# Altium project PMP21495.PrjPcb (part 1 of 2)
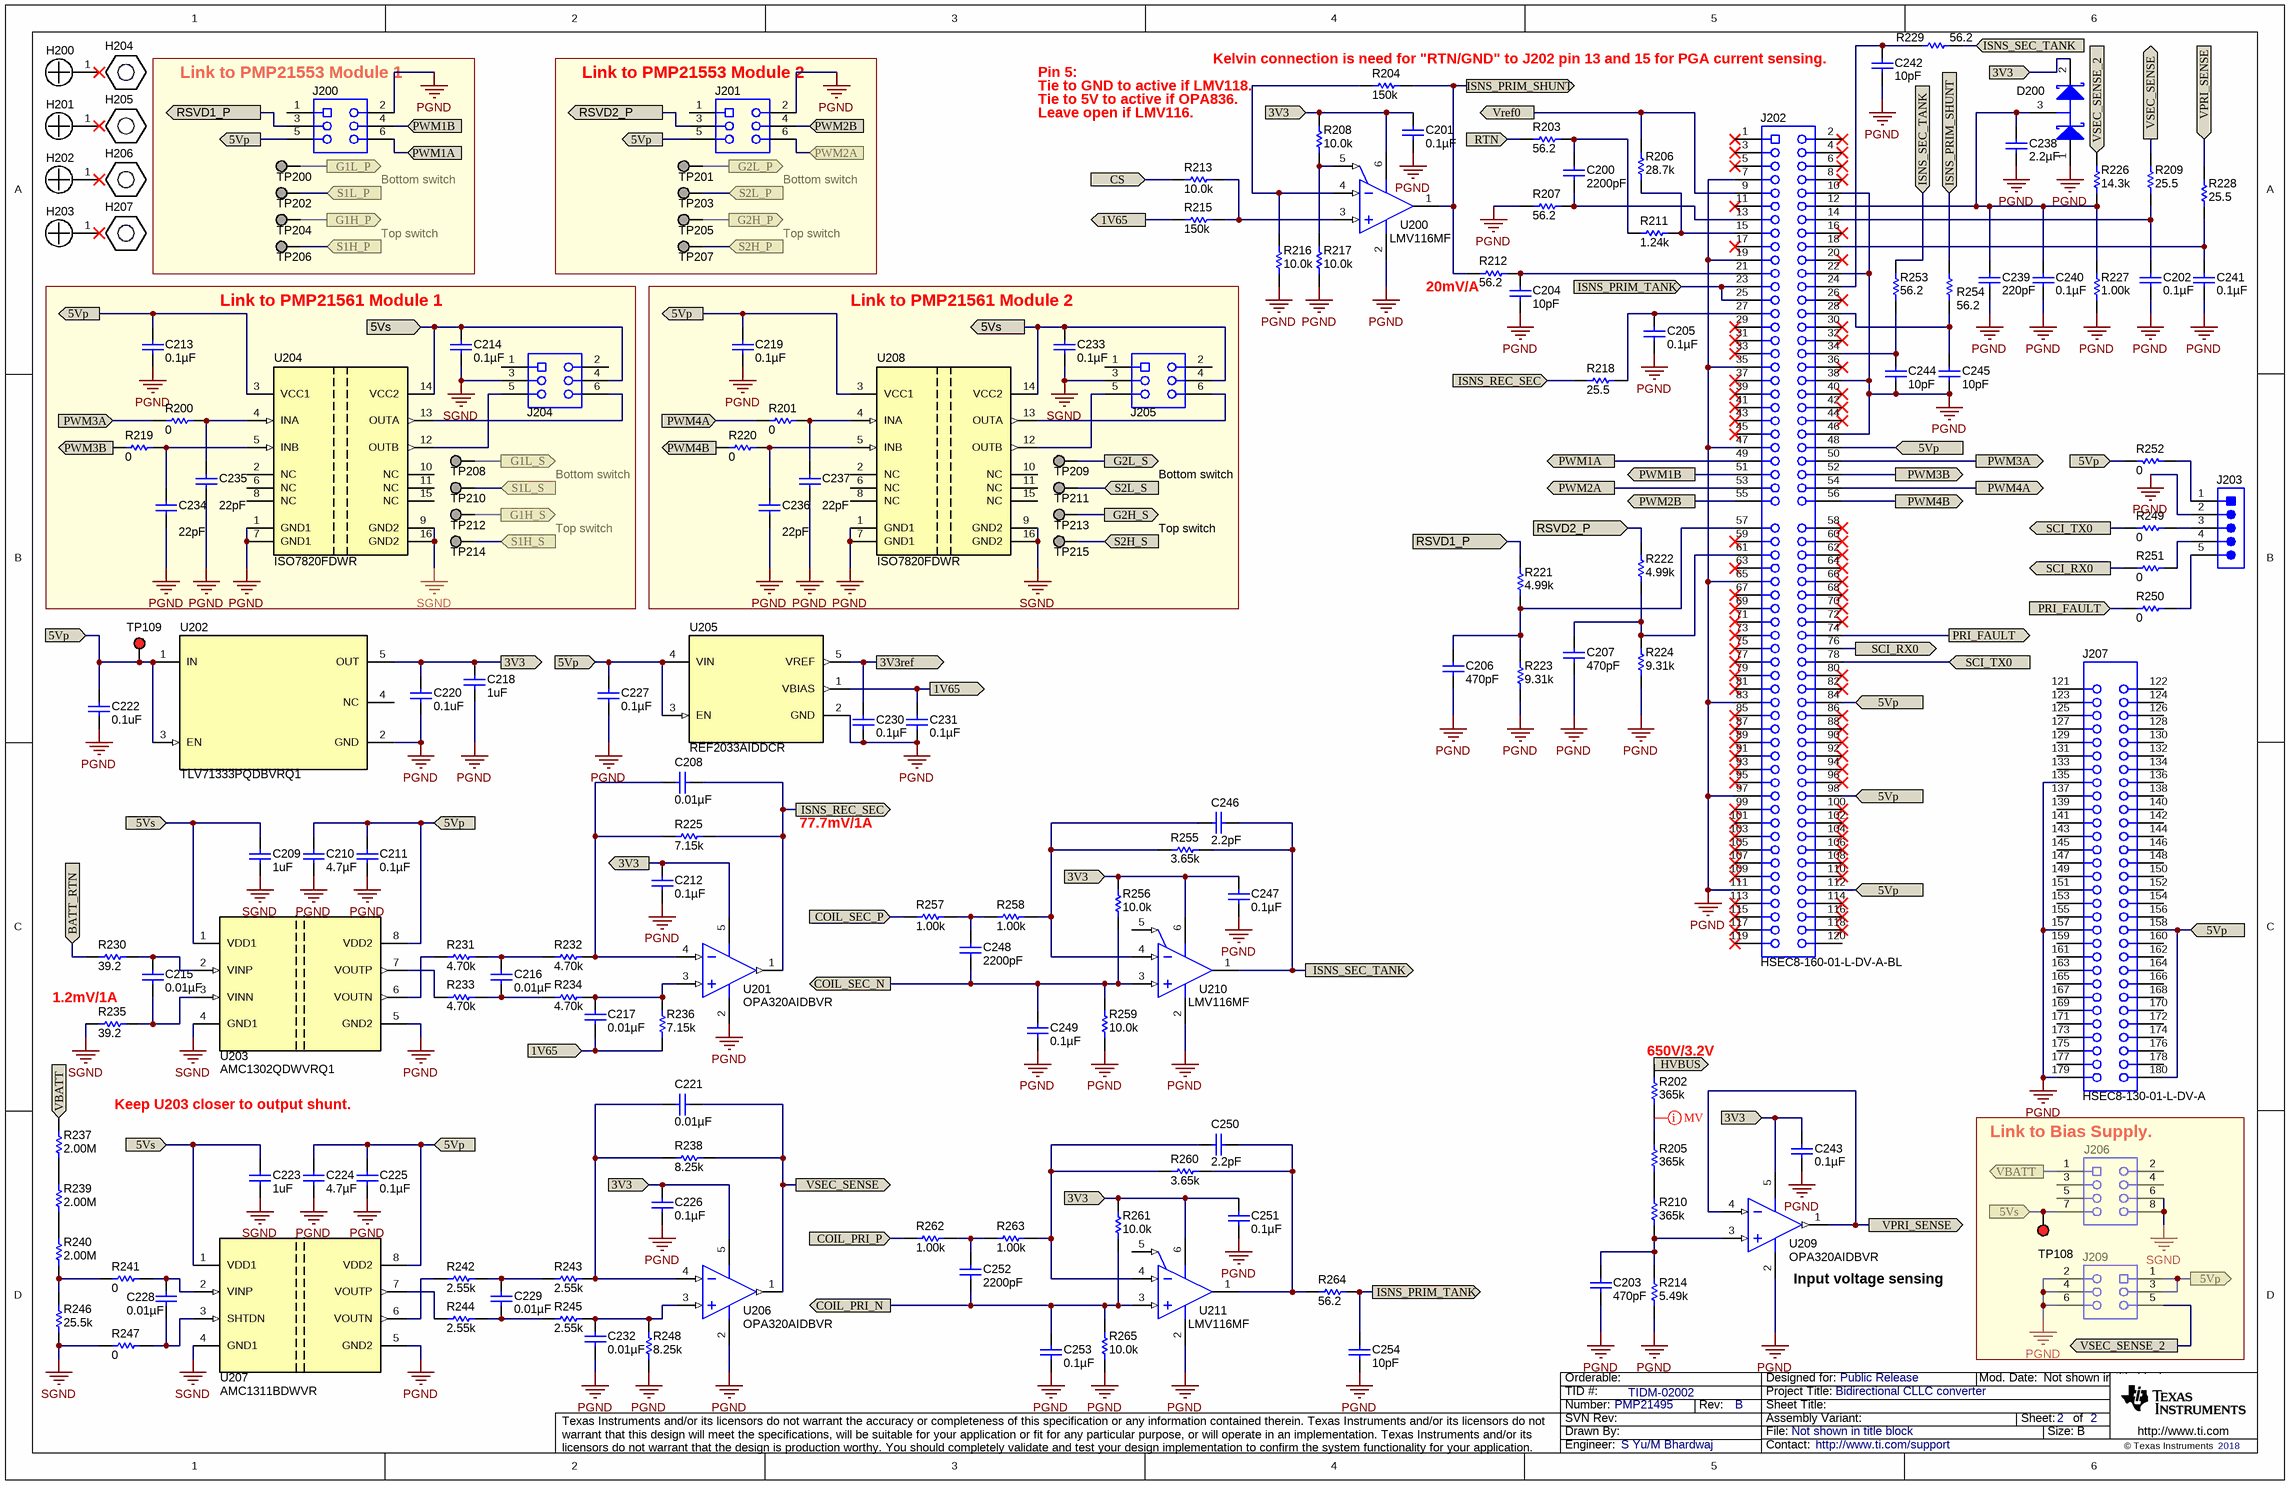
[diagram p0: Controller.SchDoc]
TID: TIDM-02002; TechSupport: http://www.ti.com/support; SCH_Rev: B; PRJ_Title: Bidirectional CLLC converter; PRJ_Number: PMP21495; PRJ_Engineer: S Yu/M Bhardwaj; PRJ_Customer: Public Release; PCB_Rev: B; PCB_Layout: Sheng-Yang Yu; CopyrightYear: 2018
2 sheets, 318 parts. Net scope: flat (ports and power ports of the same name join across sheets).
Board file: PMP21495.PcbDoc
Sheets:
  Controller.SchDoc
  PowerStage.SchDoc

## Sheet Controller.SchDoc
size 431 x 279 mm; Date: Not shown in title block; ApprovedBy: Not shown in title block; CheckedBy: Not shown in title block; Author: Not shown in title block; CompanyName: Not shown in title block; Engineer: Not shown in title block; Organization: Not shown in title block; Address1: Not shown in title block; Address2: Not shown in title block; Address3: Not shown in title block; Address4: Not shown in title block; DocumentNumber: 2; Revision: Use project parameter SCH_Rev; SheetNumber: 2; SheetTotal: 2; PageSetup: Record=PageOptions¦CenterHorizontal=True¦CenterVertical=True¦PrintScale=1.00¦XCorrection=1.00¦YCorrection=1.00¦PrintKind=0¦BorderSize=5000000¦LeftOffset=0¦BottomOffset=0¦Orientation=2¦PaperLength=1000¦PaperWidth=1000¦Scale=100¦PaperSource=15¦PrintQuality=600¦MediaType=1¦DitherType=10¦PaperKind=Letter¦PrintScaleMode=1

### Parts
C200  ValueDisplayed: 2200pF  [0402]  (hidden comment: C0402C222K9RAC7867)
C201  ValueDisplayed: 0.1µF  [0603]  (hidden comment: 06033C104JAT2A)
C202  ValueDisplayed: 0.1µF  [0603]  (hidden comment: 06033C104JAT2A)
C203  ValueDisplayed: 470pF  [0402]  (hidden comment: CGA2B2X7R1H471K050BA)
C204  ValueDisplayed: 10pF  [0603]  (hidden comment: C0603C100J5GACTU)
C205  ValueDisplayed: 0.1µF  [0603]  (hidden comment: 06033C104JAT2A)
C206  ValueDisplayed: 470pF  [0402]  (hidden comment: CGA2B2X7R1H471K050BA)
C207  ValueDisplayed: 470pF  [0402]  (hidden comment: CGA2B2X7R1H471K050BA)
C208  ValueDisplayed: 0.01µF  [0402]  (hidden comment: GRM155R61A103KA01D)
C209  ValueDisplayed: 1uF  [0603]  (hidden comment: C1608X7R1E105K080AB)
C210  ValueDisplayed: 4.7µF  [0603]  (hidden comment: CGB3B1X5R1A475K055AC)
C211  ValueDisplayed: 0.1µF  [0603]  (hidden comment: 06033C104JAT2A)
C212  ValueDisplayed: 0.1µF  [0402]  (hidden comment: C1005X7R1E104M050BB)
C213  ValueDisplayed: 0.1µF  [0402]  (hidden comment: C1005X7R1E104M050BB)
C214  ValueDisplayed: 0.1µF  [0402]  (hidden comment: C1005X7R1E104M050BB)
C215  ValueDisplayed: 0.01µF  [0603]  (hidden comment: 06031C103KAT2A)
C216  ValueDisplayed: 0.01µF  [0402]  (hidden comment: GRM155R61A103KA01D)
C217  ValueDisplayed: 0.01µF  [0402]  (hidden comment: GRM155R61A103KA01D)
C218  ValueDisplayed: 1uF  [0603]  (hidden comment: C1608X7R1E105K080AB)
C219  ValueDisplayed: 0.1µF  [0402]  (hidden comment: C1005X7R1E104M050BB)
C220  ValueDisplayed: 0.1uF  [0402]  (hidden comment: CC0402KRX7R5BB104)
C221  ValueDisplayed: 0.01µF  [0402]  (hidden comment: GRM155R61A103KA01D)
C222  ValueDisplayed: 0.1uF  [0402]  (hidden comment: CC0402KRX7R5BB104)
C223  ValueDisplayed: 1uF  [0603]  (hidden comment: C1608X7R1E105K080AB)
C224  ValueDisplayed: 4.7µF  [0603]  (hidden comment: CGB3B1X5R1A475K055AC)
C225  ValueDisplayed: 0.1µF  [0603]  (hidden comment: 06033C104JAT2A)
C226  ValueDisplayed: 0.1µF  [0402]  (hidden comment: C1005X7R1E104M050BB)
C227  ValueDisplayed: 0.1µF  [0603]  (hidden comment: 06033C104JAT2A)
C228  ValueDisplayed: 0.01µF  [0603]  (hidden comment: 06031C103KAT2A)
C229  ValueDisplayed: 0.01µF  [0402]  (hidden comment: GRM155R61A103KA01D)
C230  ValueDisplayed: 0.1µF  [0603]  (hidden comment: 06033C104JAT2A)
C231  ValueDisplayed: 0.1µF  [0603]  (hidden comment: 06033C104JAT2A)
C232  ValueDisplayed: 0.01µF  [0402]  (hidden comment: GRM155R61A103KA01D)
C233  ValueDisplayed: 0.1µF  [0402]  (hidden comment: C1005X7R1E104M050BB)
C234  ValueDisplayed: 22pF  [0402]  (hidden comment: CL05C220JB5NNNC)
C235  ValueDisplayed: 22pF  [0402]  (hidden comment: CL05C220JB5NNNC)
C236  ValueDisplayed: 22pF  [0402]  (hidden comment: CL05C220JB5NNNC)
C237  ValueDisplayed: 22pF  [0402]  (hidden comment: CL05C220JB5NNNC)
C238  ValueDisplayed: 2.2µF  [0603]  (hidden comment: GRM188C80J225KE19D)
C239  ValueDisplayed: 220pF  [0402]  (hidden comment: AC0402KRX7R9BB221)
C240  ValueDisplayed: 0.1µF  [0603]  (hidden comment: 06033C104JAT2A)
C241  ValueDisplayed: 0.1µF  [0402]  (hidden comment: C1005X7R1E104M050BB)
C242  ValueDisplayed: 10pF  [0402]  (hidden comment: C0402C100C8GACTU)
C243  ValueDisplayed: 0.1µF  [0805_HV]  (hidden comment: 08053C104JAT2A)
C244  ValueDisplayed: 10pF  [0402]  (hidden comment: C0402C100C8GACTU)
C245  ValueDisplayed: 10pF  [0402]  (hidden comment: C0402C100C8GACTU)
C246  ValueDisplayed: 2.2pF  [0402]  (hidden comment: GRM1555C1H2R2BA01D)
C247  ValueDisplayed: 0.1µF  [0402]  (hidden comment: 0402YC104KAT2A)
C248  ValueDisplayed: 2200pF  [0402]  (hidden comment: CGA2B2X7R1H222K050BA)
C249  ValueDisplayed: 0.1µF  [0402]  (hidden comment: 0402YC104KAT2A)
C250  ValueDisplayed: 2.2pF  [0402]  (hidden comment: GRM1555C1H2R2BA01D)
C251  ValueDisplayed: 0.1µF  [0402]  (hidden comment: 0402YC104KAT2A)
C252  ValueDisplayed: 2200pF  [0402]  (hidden comment: CGA2B2X7R1H222K050BA)
C253  ValueDisplayed: 0.1µF  [0402]  (hidden comment: 0402YC104KAT2A)
C254  ValueDisplayed: 10pF  [0402]  (hidden comment: C0402C100C8GACTU)
D200  BAT54S-7-F  [SOT-23]  (value not drawn)
H200  NY PMS 440 0025 PH  [NY PMS 440 0025 PH]  (value not drawn)
H201  NY PMS 440 0025 PH  [NY PMS 440 0025 PH]  (value not drawn)
H202  NY PMS 440 0025 PH  [NY PMS 440 0025 PH]  (value not drawn)
H203  NY PMS 440 0025 PH  [NY PMS 440 0025 PH]  (value not drawn)
H204  1902C  [Keystone_1902C]  (value not drawn)
H205  1902C  [Keystone_1902C]  (value not drawn)
H206  1902C  [Keystone_1902C]  (value not drawn)
H207  1902C  [Keystone_1902C]  (value not drawn)
J200  215307-3  [TE_215307-3]  (value not drawn)
J201  215307-3  [TE_215307-3]  (value not drawn)
J202  HSEC8-160-01-L-DV-A-BL  [controlCARD-120HSEC]
J203  61300511021  [Wurth_61300511021]  (value not drawn)
J204  215307-3  [TE_215307-3]  (value not drawn)
J205  215307-3  [TE_215307-3]  (value not drawn)
J206  SSW-104-24-G-D  [Samtec_SSW-104-24-x-D]  (value not drawn)
J207  HSEC8-130-01-L-DV-A  [controlCARD-180HSEC-60pinAddon]
J209  215307-3  [TE_215307-3]  (value not drawn)
R200  ValueDisplayed: 0  [0402]  (hidden comment: CRCW04020000Z0ED)
R201  ValueDisplayed: 0  [0402]  (hidden comment: CRCW04020000Z0ED)
R202  ValueDisplayed: 365k  [1206]  (hidden comment: CRCW1206365KFKEA)
R203  ValueDisplayed: 56.2  [0402]  (hidden comment: RC0402FR-0756R2L)
R204  ValueDisplayed: 150k  [0402]  (hidden comment: CRCW0402150KFKED)
R205  ValueDisplayed: 365k  [1206]  (hidden comment: CRCW1206365KFKEA)
R206  ValueDisplayed: 28.7k  [0805_HV]  (hidden comment: CRCW080528K7FKEA)
R207  ValueDisplayed: 56.2  [0402]  (hidden comment: RC0402FR-0756R2L)
R208  ValueDisplayed: 10.0k  [0402]  (hidden comment: CRCW040210K0FKED)
R209  ValueDisplayed: 25.5  [0603]  (hidden comment: CRCW060325R5FKEA)
R210  ValueDisplayed: 365k  [1206]  (hidden comment: CRCW1206365KFKEA)
R211  ValueDisplayed: 1.24k  [0402]  (hidden comment: CRCW04021K24FKED)
R212  ValueDisplayed: 56.2  [0603]  (hidden comment: CRCW060356R2FKEA)
R213  ValueDisplayed: 10.0k  [0402]  (hidden comment: CRCW040210K0FKED)
R214  ValueDisplayed: 5.49k  [0603]  (hidden comment: CRCW06035K49FKEA)
R215  ValueDisplayed: 150k  [0402]  (hidden comment: CRCW0402150KFKED)
R216  ValueDisplayed: 10.0k  [0402]  (hidden comment: CRCW040210K0FKED)
R217  ValueDisplayed: 10.0k  [0402]  (hidden comment: CRCW040210K0FKED)
R218  ValueDisplayed: 25.5  [0603]  (hidden comment: CRCW060325R5FKEA)
R219  ValueDisplayed: 0  [0402]  (hidden comment: CRCW04020000Z0ED)
R220  ValueDisplayed: 0  [0402]  (hidden comment: CRCW04020000Z0ED)
R221  ValueDisplayed: 4.99k  [0402]  (hidden comment: CRCW04024K99FKED)
R222  ValueDisplayed: 4.99k  [0402]  (hidden comment: CRCW04024K99FKED)
R223  ValueDisplayed: 9.31k  [0402]  (hidden comment: CRCW04029K31FKED)
R224  ValueDisplayed: 9.31k  [0402]  (hidden comment: CRCW04029K31FKED)
R225  ValueDisplayed: 7.15k  [0603]  (hidden comment: CRCW06037K15FKEA)
R226  ValueDisplayed: 14.3k  [0603]  (hidden comment: CRCW060314K3FKEA)
R227  ValueDisplayed: 1.00k  [0603]  (hidden comment: CRCW06031K00FKEA)
R228  ValueDisplayed: 25.5  [0603]  (hidden comment: CRCW060325R5FKEA)
R229  ValueDisplayed: 56.2  [0402]  (hidden comment: RC0402FR-0756R2L)
R230  ValueDisplayed: 39.2  [0603]  (hidden comment: CRCW060339R2FKEA)
R231  ValueDisplayed: 4.70k  [0402]  (hidden comment: RC0402FR-074K7L)
R232  ValueDisplayed: 4.70k  [0402]  (hidden comment: RC0402FR-074K7L)
R233  ValueDisplayed: 4.70k  [0402]  (hidden comment: RC0402FR-074K7L)
R234  ValueDisplayed: 4.70k  [0402]  (hidden comment: RC0402FR-074K7L)
R235  ValueDisplayed: 39.2  [0603]  (hidden comment: CRCW060339R2FKEA)
R236  ValueDisplayed: 7.15k  [0402]  (hidden comment: CRCW04027K15FKED)
R237  ValueDisplayed: 2.00M  [1206]  (hidden comment: RC1206FR-072ML)
R238  ValueDisplayed: 8.25k  [0603]  (hidden comment: CRCW06038K25FKEA)
R239  ValueDisplayed: 2.00M  [1206]  (hidden comment: RC1206FR-072ML)
R240  ValueDisplayed: 2.00M  [1206]  (hidden comment: RC1206FR-072ML)
R241  ValueDisplayed: 0  [0603]  (hidden comment: CRCW06030000Z0EA)
R242  ValueDisplayed: 2.55k  [0603]  (hidden comment: CRCW06032K55FKEA)
R243  ValueDisplayed: 2.55k  [0603]  (hidden comment: CRCW06032K55FKEA)
R244  ValueDisplayed: 2.55k  [0603]  (hidden comment: CRCW06032K55FKEA)
R245  ValueDisplayed: 2.55k  [0603]  (hidden comment: CRCW06032K55FKEA)
R246  ValueDisplayed: 25.5k  [0603]  (hidden comment: CRCW060325K5FKEA)
R247  ValueDisplayed: 0  [0603]  (hidden comment: CRCW06030000Z0EA)
R248  ValueDisplayed: 8.25k  [0603]  (hidden comment: CRCW06038K25FKEA)
R249  ValueDisplayed: 0  [0603]  (hidden comment: CRCW06030000Z0EA)
R250  ValueDisplayed: 0  [0603]  (hidden comment: CRCW06030000Z0EA)
R251  ValueDisplayed: 0  [0603]  (hidden comment: CRCW06030000Z0EA)
R252  ValueDisplayed: 0  [0603]  (hidden comment: CRCW06030000Z0EA)
R253  ValueDisplayed: 56.2  [0402]  (hidden comment: RC0402FR-0756R2L)
R254  ValueDisplayed: 56.2  [0402]  (hidden comment: RC0402FR-0756R2L)
R255  ValueDisplayed: 3.65k  [0402]  (hidden comment: CRCW04023K65FKED)
R256  ValueDisplayed: 10.0k  [0402]  (hidden comment: CRCW040210K0FKED)
R257  ValueDisplayed: 1.00k  [0402]  (hidden comment: CRCW04021K00FKED)
R258  ValueDisplayed: 1.00k  [0402]  (hidden comment: CRCW04021K00FKED)
R259  ValueDisplayed: 10.0k  [0402]  (hidden comment: CRCW040210K0FKED)
R260  ValueDisplayed: 3.65k  [0402]  (hidden comment: CRCW04023K65FKED)
R261  ValueDisplayed: 10.0k  [0402]  (hidden comment: CRCW040210K0FKED)
R262  ValueDisplayed: 1.00k  [0402]  (hidden comment: CRCW04021K00FKED)
R263  ValueDisplayed: 1.00k  [0402]  (hidden comment: CRCW04021K00FKED)
R264  ValueDisplayed: 56.2  [0402]  (hidden comment: RC0402FR-0756R2L)
R265  ValueDisplayed: 10.0k  [0402]  (hidden comment: CRCW040210K0FKED)
TP108  5000  [Keystone5000]  (value not drawn)
TP109  5000  [Keystone5000]  (value not drawn)
TP200  Suggest using a net name here  [Mill-Max_0312-0-15-15-34-27-10-0]  (value not drawn)
TP201  Suggest using a net name here  [Mill-Max_0312-0-15-15-34-27-10-0]  (value not drawn)
TP202  Suggest using a net name here  [Mill-Max_0312-0-15-15-34-27-10-0]  (value not drawn)
TP203  Suggest using a net name here  [Mill-Max_0312-0-15-15-34-27-10-0]  (value not drawn)
TP204  Suggest using a net name here  [Mill-Max_0312-0-15-15-34-27-10-0]  (value not drawn)
TP205  Suggest using a net name here  [Mill-Max_0312-0-15-15-34-27-10-0]  (value not drawn)
TP206  Suggest using a net name here  [Mill-Max_0312-0-15-15-34-27-10-0]  (value not drawn)
TP207  Suggest using a net name here  [Mill-Max_0312-0-15-15-34-27-10-0]  (value not drawn)
TP208  Suggest using a net name here  [Mill-Max_0312-0-15-15-34-27-10-0]  (value not drawn)
TP209  Suggest using a net name here  [Mill-Max_0312-0-15-15-34-27-10-0]  (value not drawn)
TP210  Suggest using a net name here  [Mill-Max_0312-0-15-15-34-27-10-0]  (value not drawn)
TP211  Suggest using a net name here  [Mill-Max_0312-0-15-15-34-27-10-0]  (value not drawn)
TP212  Suggest using a net name here  [Mill-Max_0312-0-15-15-34-27-10-0]  (value not drawn)
TP213  Suggest using a net name here  [Mill-Max_0312-0-15-15-34-27-10-0]  (value not drawn)
TP214  Suggest using a net name here  [Mill-Max_0312-0-15-15-34-27-10-0]  (value not drawn)
TP215  Suggest using a net name here  [Mill-Max_0312-0-15-15-34-27-10-0]  (value not drawn)
U200  LMV116MF  [DBV0006A_L]
U201  OPA320AIDBVR  [DBV0005A_N]
U202  TLV71333PQDBVRQ1  [DBV0005A_N]
U203  AMC1302QDWVRQ1  [DWV0008A]
U204  ISO7820FDWR  [DW0016B_HV]
U205  REF2033AIDDCR  [DDC0005A_N]
U206  OPA320AIDBVR  [DBV0005A_N]
U207  AMC1311BDWVR  [DWV0008A]
U208  ISO7820FDWR  [DW0016B_HV]
U209  OPA320AIDBVR  [DBV0005A_N]
U210  LMV116MF  [DBV0006A_L]
U211  LMV116MF  [DBV0006A_L]

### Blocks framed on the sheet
Link to PMP21553 Module 1: J200 TP200 TP202 TP204 TP206
Link to PMP21553 Module 2: J201 TP201 TP203 TP205 TP207
Link to PMP21561 Module 1: C213 C214 C234 C235 J204 R200 R219 TP208 TP210 TP212 TP214 U204
Link to PMP21561 Module 2: C219 C233 C236 C237 J205 R201 R220 TP209 TP211 TP213 TP215 U208
Link to Bias Supply.: J206 J209 TP108

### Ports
1V65, 1V65 (in), 1V65 (out), 3V3, 3V3 (in), 3V3 (out), 3V3ref (out), 5Vp, 5Vp (in), 5Vs, BATT_RTN, COIL_PRI_N (out), COIL_PRI_P (in), COIL_SEC_N (out), COIL_SEC_P (in), CS (in), G1H_P (out), G1H_S (out), G1L_P (out), G1L_S (out), G2H_P (out), G2H_S (out), G2L_P (out), G2L_S (out), HVBUS (in), ISNS_PRIM_SHUNT (in), ISNS_PRIM_SHUNT (out), ISNS_PRIM_TANK (in), ISNS_PRIM_TANK (out), ISNS_REC_SEC (in), ISNS_REC_SEC (out), ISNS_SEC_TANK (in), ISNS_SEC_TANK (out), PRI_FAULT (in), PRI_FAULT (out), PWM1A, PWM1A (in), PWM1B, PWM1B (in), PWM2A (in), PWM2A (out), PWM2B (in), PWM2B (out), PWM3A (in), PWM3A (out), PWM3B (in), PWM3B (out), PWM4A (in), PWM4A (out), PWM4B (in), PWM4B (out), RSVD1_P (in), RSVD1_P (out), RSVD2_P (in), RSVD2_P (out), RTN (in), S1H_P, S1H_S, S1L_P, S1L_S, S2H_P, S2H_S, S2L_P, S2L_S, SCI_RX0 (out), SCI_TX0, VBATT, VBATT (in), VPRI_SENSE (in), VPRI_SENSE (out), Vref0 (out), VSEC_SENSE, VSEC_SENSE_2, VSEC_SENSE_2 (out)

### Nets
PGND: C201.1 C202.1 C203.2 C204.2 C205.2 C206.2 C207.2 C210.2 C211.1 C212.2 C213.2 C218.1 C219.2 C220.2 C222.2 C224.2 C225.1 C226.2 C227.1 C230.1 C231.1 C232.2 C234.2 C235.2 C236.2 C237.2 C238.2 C239.2 C240.2 C241.2 C242.2 C243.2 C244.2 C245.2 C247.2 C249.2 C251.2 C253.2 C254.2 D200.1(A) J200.2 J201.2 J202.7 J202.10 J202.19 J202.22 J202.35 J202.38 J202.46 J202.47 J202.65 J202.83 J202.97 J202.111 J203.2 J207.135 J207.157 J207.179 J209.2 J209.4 J209.6 R207.1 R214.1 R216.1 R217.1 R223.1 R224.1 R227.1 R248.1 R259.1 R265.1 U200.2(VS-) U201.2(V-) U202.2(GND) U203.5(GND2) U204.1(GND1) U204.7(GND1) U205.2(GND) U206.2(V-) U207.5(GND2) U208.1(GND1) U208.7(GND1) U209.2(V-) U210.2(VS-) U211.2(VS-)
SGND: C209.1 C214.2 C223.1 C233.2 J204.3 J205.3 J206.6 J206.8 R235.1 R246.1 R247.1 U203.4(GND1) U204.9(GND2) U204.16(GND2) U207.4(GND1) U208.9(GND2) U208.16(GND2)
1V65: C217.2 C231.2 R215.1 R236.1 U205.1(VBIAS) ; port 1V65
3V3: C201.2 C212.1 C218.2 C220.1 C226.1 C243.1 C247.1 C251.1 D200.2(K) R208.2 R256.2 R261.2 U200.6(VS+) U201.5(V+) U202.5(OUT) U206.5(V+) U209.5(V+) U210.6(VS+) U211.6(VS+) ; port 3V3
3V3ref: C230.2 U205.5(VREF) ; port 3V3ref
5Vp: C210.1 C211.2 C213.1 C219.1 C222.1 C224.1 C225.2 C227.2 J200.5 J201.5 J202.48 J202.84 J202.98 J202.112 J207.158 J207.180 J209.1 J209.3 R252.2 TP109.1 U202.1(IN) U202.3(EN) U203.8(VDD2) U204.3(VCC1) U205.3(EN) U205.4(VIN) U207.8(VDD2) U208.3(VCC1) ; port 5Vp
5Vs: C209.2 C214.1 C223.2 C233.1 J204.4 J205.4 J206.7 TP108.1 U203.1(VDD1) U204.14(VCC2) U207.1(VDD1) U208.14(VCC2) ; port 5Vs
BATT_RTN: R230.1 ; port BATT_RTN
COIL_PRI_N: C252.2 C253.1 R261.1 R265.2 U211.3(VIN+) ; port COIL_PRI_N
COIL_PRI_P: R262.1 ; port COIL_PRI_P
COIL_SEC_N: C248.2 C249.1 R256.1 R259.2 U210.3(VIN+) ; port COIL_SEC_N
COIL_SEC_P: R257.1 ; port COIL_SEC_P
CS: R213.2 ; port CS
G1H_P: TP204.1 ; port G1H_P
G1H_S: TP212.1 ; port G1H_S
G1L_P: TP200.1 ; port G1L_P
G1L_S: TP208.1 ; port G1L_S
G2H_P: TP205.1 ; port G2H_P
G2H_S: TP213.1 ; port G2H_S
G2L_P: TP201.1 ; port G2L_P
G2L_S: TP209.1 ; port G2L_S
HVBUS: R202.2 ; port HVBUS
ISNS_PRIM_SHUNT: R204.2 R212.1 R254.2 U200.1(VOUT) ; port ISNS_PRIM_SHUNT
ISNS_PRIM_TANK: C254.1 J202.23 J202.25 R264.1 ; port ISNS_PRIM_TANK
ISNS_REC_SEC: C208.1 R218.2 R225.2 U201.1(OUT) ; port ISNS_REC_SEC
ISNS_SEC_TANK: C246.1 R229.2 R253.2 R255.2 U210.1(VOUT) ; port ISNS_SEC_TANK
PRI_FAULT: J202.74 R250.1 ; port PRI_FAULT
PWM1A: J200.6 J202.49 ; port PWM1A
PWM1B: J200.4 J202.51 ; port PWM1B
PWM2A: J201.6 J202.53 ; port PWM2A
PWM2B: J201.4 J202.55 ; port PWM2B
PWM3A: J202.50 R200.1 ; port PWM3A
PWM3B: J202.52 R219.1 ; port PWM3B
PWM4A: J202.54 R201.1 ; port PWM4A
PWM4B: J202.56 R220.1 ; port PWM4B
RSVD1_P: J200.3 R221.2 ; port RSVD1_P
RSVD2_P: J201.3 R222.2 ; port RSVD2_P
RTN: R203.1 ; port RTN
S1H_P: TP206.1 ; port S1H_P
S1H_S: TP214.1 ; port S1H_S
S1L_P: TP202.1 ; port S1L_P
S1L_S: TP210.1 ; port S1L_S
S2H_P: TP207.1 ; port S2H_P
S2H_S: TP215.1 ; port S2H_S
S2L_P: TP203.1 ; port S2L_P
S2L_S: TP211.1 ; port S2L_S
SCI_RX0: J202.76 R251.1 ; port SCI_RX0
SCI_TX0: J202.78 R249.1 ; port SCI_TX0
VBATT: J206.1 R237.2 ; port VBATT
VPRI_SENSE: R228.2 U209.1(OUT) U209.4(IN-) ; port VPRI_SENSE
Vref0: J202.9 R206.2 ; port Vref0
VSEC_SENSE: C221.1 R209.2 R238.2 U206.1(OUT) ; port VSEC_SENSE
VSEC_SENSE_2: J209.5 R226.2 ; port VSEC_SENSE_2
NetC200_1: C200.1 R203.2 R211.1
NetC200_2: C200.2 J202.13 R207.2
NetC202_2: C202.2 J202.14 R209.1
NetC203_1: C203.1 R210.1 R214.2 U209.3(IN+)
NetC204_1: C204.1 J202.21 R212.2
NetC205_1: C205.1 J202.27 R218.1
NetC206_1: C206.1 J202.57 R221.1 R223.2
NetC207_1: C207.1 J202.61 R222.1 R224.2
NetC208_2: C208.2 R225.1 R232.2 U201.4(IN-)
NetC215_1: C215.1 R230.2 U203.2(VINP)
NetC215_2: C215.2 R235.2 U203.3(VINN)
NetC216_1: C216.1 R231.2 R232.1
NetC216_2: C216.2 R233.2 R234.1
NetC217_1: C217.1 R234.2 R236.2 U201.3(IN+)
NetC221_2: C221.2 R238.1 R243.2 U206.4(IN-)
NetC228_1: C228.1 R241.2 U207.2(VINP)
NetC228_2: C228.2 R247.2 U207.3(SHTDN)
NetC229_1: C229.1 R242.2 R243.1
NetC229_2: C229.2 R244.2 R245.1
NetC232_1: C232.1 R245.2 R248.2 U206.3(IN+)
NetC234_1: C234.1 R219.2 U204.5(INB)
NetC235_1: C235.1 R200.2 U204.4(INA)
NetC236_1: C236.1 R220.2 U208.5(INB)
NetC237_1: C237.1 R201.2 U208.4(INA)
NetC238_1: C238.1 C239.1 C240.1 D200.3(C) J202.12 R226.1 R227.2
NetC241_1: C241.1 J202.18 R228.1
NetC242_1: C242.1 J202.24 R229.1
NetC244_1: C244.1 J202.34 R253.1
NetC245_1: C245.1 J202.28 R254.1
NetC246_2: C246.2 R255.1 R258.2 U210.4(VIN-)
NetC248_1: C248.1 R257.2 R258.1
NetC250_1: C250.1 R260.2 R264.2 U211.1(VOUT)
NetC250_2: C250.2 R260.1 R263.2 U211.4(VIN-)
NetC252_1: C252.1 R262.2 R263.1
NetJ202_15: J202.15 R206.1 R211.2
NetJ203_1: J203.1 R252.1
NetJ203_3: J203.3 R249.2
NetJ203_4: J203.4 R251.2
NetJ203_5: J203.5 R250.2
NetJ204_5: J204.5 U204.12(OUTB)
NetJ204_6: J204.6 U204.13(OUTA)
NetJ205_5: J205.5 U208.12(OUTB)
NetJ205_6: J205.6 U208.13(OUTA)
NetR202_1: R202.1 R205.2
NetR204_1: R204.1 R216.2 U200.4(VIN-)
NetR205_1: R205.1 R210.2
NetR208_1: R208.1 R217.2 U200.5(~{PD})
NetR213_1: R213.1 R215.2 U200.3(VIN+)
NetR231_1: R231.1 U203.6(VOUTN)
NetR233_1: R233.1 U203.7(VOUTP)
NetR237_1: R237.1 R239.2
NetR239_1: R239.1 R240.2
NetR240_1: R240.1 R241.1 R246.2
NetR242_1: R242.1 U207.6(VOUTN)
NetR244_1: R244.1 U207.7(VOUTP)

Not connected (* = marked no-connect by the designer): H200 1*; H201 1*; H202 1*; H203 1*; J200 1; J201 1; J202 1* 2* 3* 4* 5* 6* 8* 11* 16* 17* 20* 26* 29* 30* 31* 32* 33* 36* 37* 39* 40* 41* 42* 43* 44* 45* 58* 59* 60* 62* 63* 64* 66* 67* 68* 69* 70* 71* 72* 73* 75* 77* 79* 80* 81* 82* 85* 86* 87* 88* 89* 90* 91* 92* 93* 94* 95* 96* 99* 100* 101* 102* 103* 104* 105* 106* 107* 108* 109* 110* 113* 114* 115* 116* 117* 118* 119* 120; J204 1 2; J205 1 2; J206 2 3 4 5; J207 121 122 123 124 125 126 127 128 129 130 131 132 133 134 136 137 138 139 140 141 142 143 144 145 146 147 148 149 150 151 152 153 154 155 156 159 160 161 162 163 164 165 166 167 168 169 170 171 172 173 174 175 176 177 178; U202 4(NC); U204 2(NC) 6(NC) 8(NC) 10(NC) 11(NC) 15(NC); U208 2(NC) 6(NC) 8(NC) 10(NC) 11(NC) 15(NC); U210 5(~{PD}); U211 5(~{PD})

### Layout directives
net class MV: NetR202_1

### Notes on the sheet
- Pin 5:
- Tie to GND to active if LMV118.
- Tie to 5V to active if OPA836.
- (near R204) Kelvin connection is need for "RTN/GND" to J202 pin 13 and 15 for PGA current sensing.
- Leave open if LMV116.
- Top switch
- (near J200) Bottom switch
- (near J201) Bottom switch
- (near R212) 20mV/A
- Bottom switch
- 77.7mV/1A
- 1.2mV/1A
- Keep U203 closer to output shunt.
- (near R202) 650V/3.2V
- (near U209) Input voltage sensing

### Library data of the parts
C200 = GRM155R60J222KA01D: CAP CER 2200PF 6.3V X7R 0402; Manufacturer: KEMET; Polarized: N; CompType: Capacitor; U/M: EA; Cap_F: 0.0000000022; Tolerance_%: 10; VDC_V: 6.3; TaMin_C: -55; TaMax_C: 85; SizeArea_mm2: 0.5; SizeAreaWB_mm2: 3; SizeX_mm: 1; SizeZ_mm: 0.6; AEC Category: Q200
C201 C202 C205 C211 C225 C227 C230 C231 C240 = 06033C104JAT2A: CAP, CERM, 0.1uF, 25V, +/-5%, X7R, 0603; Manufacturer: AVX; Polarized: N; CompType: Capacitor; U/M: EA; Cap_F: 0.0000001; Tolerance_%: 5; ESR_Ohm: 0.05; Value1: 0.05 ohm; VDC_V: 25; TaMin_C: -55; TaMax_C: 125
C203 C206 C207 = CGA2B2X7R1H471K050BA: CAP, CERM, 470 pF, 50 V,+/- 10%, X7R, AEC-Q200 Grade 1, 0402; Manufacturer: TDK; Polarized: N; CompType: Capacitor; Value: 470pF; U/M: EA; Cap_F: 0.00000000047; Tolerance_%: 10; ESR_ohm: 4.96489; Value1: 4.96489 ohm; VDC_V: 50; Value2: 50V; IRMS_A: 0.228414; TaMin_C: -55; TaMax_C: 125; SizeArea_mm2: 0.5; SizeAreaWB_mm2: 3; SizeX_mm: 1; SizeZ_mm: 0.6; AEC Category: Q200; AEC Qualified: Y
C204 = C0603C100J5GACTU: CAP, CERM, 10 pF, 50 V,+/- 5%, C0G/NP0, 0603; Manufacturer: Kemet; Polarized: N; CompType: Capacitor; Value: 10pF; U/M: EA; Cap_F: 0.00000000001; Tolerance_%: 5; VDC_V: 50; Value2: 50V; TaMin_C: -55; TaMax_C: 125; SizeArea_mm2: 1.28; SizeAreaWB_mm2: 4.68; SizeX_mm: 1.6; SizeY_mm: 0.8; SizeZ_mm: 1; AEC Category: Q200; Green_Lifecycle: Active; Green_REACh: Passed
C208 C216 C217 C221 C229 C232 = GRM155R61A103KA01D: CAP, CERM, 0.01 µF, 10 V,+/- 10%, X5R, 0402; Manufacturer: MuRata; Polarized: N; CompType: Capacitor; Value: 0.01uF; U/M: EA; Cap_F: 0.00000001; Tolerance_%: 10; Value2: 10V; TaMin_C: -55; TaMax_C: 85; SizeArea_mm2: 0.5; SizeAreaWB_mm2: 3; SizeX_mm: 1; SizeZ_mm: 0.6; AEC Category: Q200; Green_Lifecycle: Active; Green_REACh: Passed
C209 C218 C223 = C1608X7R1E105K080AB: CAP, CERM, 1uF, 25V, +/-10%, X7R, 0603; Manufacturer: TDK; Polarized: N; CompType: Capacitor; U/M: EA; Cap_F: 0.000001; Tolerance_%: 10; Value1: Unknown; VDC_V: 25; TaMin_C: -55; TaMax_C: 125
C210 C224 = CGB3B1X5R1A475K055AC: CAP, CERM, 4.7 µF, 10 V,+/- 10%, X5R, 0603; Manufacturer: TDK; Polarized: N; CompType: Capacitor; Value: 4.7uF; U/M: EA; Cap_F: 0.0000047; Tolerance_%: 10; Value2: 10V; TaMin_C: -55; TaMax_C: 85; SizeArea_mm2: 1.28; SizeAreaWB_mm2: 4.68; SizeX_mm: 1.6; SizeY_mm: 0.8; SizeZ_mm: 1; AEC Category: Q200; Green_Lifecycle: Active; Green_REACh: Passed
C212-C214 C219 C226 C233 C241 = C1005X7R1E104M050BB: CAP, CERM, 0.1 µF, 25 V,+/- 20%, X7R, 0402; Manufacturer: TDK; Polarized: N; CompType: Capacitor; Value: 0.1uF; U/M: EA; Cap_F: 0.0000001; Tolerance_%: 20; VDC_V: 25; Value2: 25V; TaMin_C: -55; TaMax_C: 125; SizeArea_mm2: 0.5; SizeAreaWB_mm2: 3; SizeX_mm: 1; SizeZ_mm: 0.6; AEC Category: Q200; Green_Lifecycle: NRND; Green_REACh: Passed
C215 C228 = 06031C103KAT2A: CAP, CERM, 0.01 µF, 100 V,+/- 10%, X7R, 0603; Manufacturer: AVX; Polarized: N; CompType: Capacitor; Value: 0.01uF; U/M: EA; Cap_F: 0.00000001; Tolerance_%: 10; ESR_ohm: 0.098; Value1: 0.098 ohm; VDC_V: 100; Value2: 100V; TaMin_C: -55; TaMax_C: 125; SizeArea_mm2: 1.28; SizeAreaWB_mm2: 4.68; SizeX_mm: 1.6; SizeY_mm: 0.8; SizeZ_mm: 1; AEC Category: Q200; Green_Lifecycle: Active; Green_REACh: Passed
C220 C222 = GRM155R70J104KA01D: CAP, CERM, 0.1uF, 6.3V, +/-10%, X7R, 0402; Manufacturer: Yageo; Polarized: N; CompType: Capacitor; U/M: EA; Cap_F: 0.0000001; Tolerance_%: 10; Value1: Unknown; VDC_V: 6.3; TaMin_C: -55; TaMax_C: 125
C234-C237 = CMP-0085851-1: CAP, CERM, 22 pF, 50 V,+/- 5%, C0G/NP0, 0402; Manufacturer: Walsin; AEC Qualified: N; TaMax_C: 125°C; SizeX_mm: 1; Value: 22pF; SizeZ_mm: 0.6; Value2: 50V; AEC Category: Q200; CompType: Capacitor; TaMin_C: -55°C; SizeArea_mm2: 0.5; SizeAreaWB_mm2: 3; U/M: EA
C238 = GRM188C80J225KE19D: CAP, CERM, 2.2 µF, 6.3 V,+/- 10%, X6S, 0603; Manufacturer: MuRata; Polarized: N; CompType: Capacitor; Value: 2.2uF; U/M: EA; Cap_F: 0.0000022; Tolerance_%: 10; VDC_V: 6.3; Value2: 6.3V; TaMin_C: -55; TaMax_C: 105; SizeArea_mm2: 1.28; SizeAreaWB_mm2: 4.68; SizeX_mm: 1.6; SizeY_mm: 0.8; SizeZ_mm: 1; AEC Category: Q200
C239 = GRM1555C1H221JA01D: CAP, CERM, 220 pF, 50 V,+/- 5%, C0G/NP0, 0402; Manufacturer: Yageo; Polarized: N; CompType: Capacitor; Value: 220pF; U/M: EA; Cap_F: 0.00000000022; Tolerance_%: 5; VDC_V: 50; Value2: 50V; TaMin_C: -55; TaMax_C: 125; SizeArea_mm2: 0.5; SizeAreaWB_mm2: 3; SizeX_mm: 1; SizeZ_mm: 0.6; AEC Category: Q200; Green_Lifecycle: Active; Green_REACh: Passed
C242 C244 C245 C254 = C0402C100C8GACTU: CAP, CERM, 10 pF, 10 V,+/- 2.5%, C0G/NP0, 0402; Manufacturer: Kemet; Polarized: N; CompType: Capacitor; Value: 10pF; U/M: EA; Cap_F: 0.00000000001; Tolerance_%: 2.5; VDC_V: 10; Value2: 10V; TaMin_C: -55; TaMax_C: 125; SizeArea_mm2: 0.5; SizeAreaWB_mm2: 3; SizeX_mm: 1; SizeZ_mm: 0.6; AEC Category: Q200
C243 = 08053C104JAT2A: CAP, CERM, 0.1 µF, 25 V,+/- 5%, X7R, 0805; Manufacturer: AVX; Polarized: N; CompType: Capacitor; Value: 0.1uF; U/M: EA; Cap_F: 0.0000001; Tolerance_%: 5; VDC_V: 25; Value2: 25V; TaMin_C: -55; TaMax_C: 125; Cap_Case: 0805; SizeArea_mm2: 2.5; SizeAreaWB_mm2: 6.75; SizeX_mm: 2; SizeY_mm: 1.25; SizeZ_mm: 1.45; AEC Category: Q200
C246 C250 = GRM1555C1H2R2BA01D: CAP, CERM, 2.2 pF, 50 V,+/- 5%, C0G/NP0, 0402; Manufacturer: MuRata; Polarized: N; CompType: Capacitor; Value: 2.2pF; U/M: EA; Cap_F: 0.0000000000022; Tolerance_%: 5; VDC_V: 50; Value2: 50V; TaMin_C: -55; TaMax_C: 125; SizeArea_mm2: 0.5; SizeAreaWB_mm2: 3; SizeX_mm: 1; SizeZ_mm: 0.6; AEC Category: Q200
C247 C249 C251 C253 = 0402YC104KAT2A: CAP, CERM, 0.1 µF, 16 V,+/- 10%, X7R, 0402; Manufacturer: AVX; Polarized: N; CompType: Capacitor; Value: 0.1uF; U/M: EA; Cap_F: 0.0000001; Tolerance_%: 10; VDC_V: 16; Value2: 16V; TaMin_C: -55; TaMax_C: 125; SizeArea_mm2: 0.5; SizeAreaWB_mm2: 3; SizeX_mm: 1; SizeZ_mm: 0.6; AEC Category: Q200; Green_Lifecycle: Active; Green_REACh: Passed
C248 C252 = CGA2B2X7R1H222K050BA: CAP, CERM, 2200 pF, 50 V,+/- 10%, X7R, AEC-Q200 Grade 1, 0402; Manufacturer: TDK; Polarized: N; CompType: Capacitor; Value: 2200pF; U/M: EA; Cap_F: 0.0000000022; Tolerance_%: 10; ESR_ohm: 1.07794; Value1: 1.07794 ohm; VDC_V: 50; Value2: 50V; IRMS_A: 0.264071; TaMin_C: -55; TaMax_C: 125; SizeArea_mm2: 0.5; SizeAreaWB_mm2: 3; SizeX_mm: 1; SizeZ_mm: 0.6; AEC Category: Q200; AEC Qualified: Y
D200 = CMP-0028456-1: Diode, Schottky, 30 V, 0.2 A, SOT-23; Manufacturer: Diodes Inc.; Io_A: 2dA; Green_Lifecycle: Active; SizeAreaWB_mm2: 14; Vr_V: 30V; Green_REACh: Passed; Value1: 0.2A; TJmax_C: 125°C; U/M: EA; Value: 30V; SizeZ_mm: 1.1; SizeX_mm: 2.5; SizeY_mm: 3; Vf_V: 6.5dV; Value2: 0.65V; SizeArea_mm2: 7.5; AEC Category: Q101
H200-H203 = CMP-0003617-1: Machine Screw, Round, #4-40 x 1/4, Nylon, Philips panhead; Manufacturer: B&F Fastener Supply; CompType: Hardware
H204-H207 = CMP-0003610-1: Standoff, Hex, 0.5"L #4-40 Nylon; Manufacturer: Keystone; CompType: Hardware
J200 J201 J204 J205 J209 = CMP-0082603-1: Receptacle, 2.54mm, 3x2, Tin, TH; Manufacturer: TE Connectivity; Pitch_mm: 2.54; Gender: Female; Cert_UL: Y; Row_Count: 2; CompType: Socket Strip
J202 = controlCARD-120HSEC: C2000 controlCARD-120HSEC connector, SMT; Manufacturer: Samtec; SymbolCreator: a0412235; Note: The pin numbering does not match Samtec datasheet
J203 = CMP-0054800-1: Header, 2.54 mm, 5x1, Gold, R/A, TH; Manufacturer: Wurth Elektronik; CNHeader: TRUE; Shrouded: N; Gender: Male; Row_Count: 1; Pitch_mm: 2.54; CT: FALSE
J206 = CMP-0055706-1: Receptacle, 2.54mm, 4x2, Gold, TH; Manufacturer: Samtec; CNHeader: FALSE; Current_A: 4.7A; Gender: Female; Cert_CSA: Y; Voltage_V: 465V; CompType: Socket Strip; Row_Count: 2; RowSpacing_mm: 2.54; CT: TRUE
J207 = CMP-0003859-2: C2000 controlCARD-180HSEC (60-pin addon) connector, SMT; Manufacturer: Samtec; Note: The pin numbering does not match Samtec datasheet
R200 R201 R219 R220 = CRCW04020000Z0ED: RES, 0, 5%, 0.063 W, 0402; Manufacturer: Vishay-Dale; CompType: Resistor; Value: 0; Value_Code: 0000; Tolerance_%: 5; Power_W: 0.063; Value2: 0.063W; VDC_V: 50; TempCo: 200 ppm/C; SizeArea_mm2: 0.5; SizeX_mm: 1; SizeZ_mm: 0.6; EIA_Code: E24; U/M: EA; AEC Category: Q200; Green_Lifecycle: Active; Green_REACh: Passed
R202 R205 R210 = CMP-0016927-3: RES, 365 k, 1%, 0.25 W, AEC-Q200 Grade 0, 1206; Manufacturer: Vishay-Dale; Power_W: 250mW; TempCo: 100 ppm/C; Value: 365k; EIA_Code: E96; SizeX_mm: 3.2; SizeY_mm: 1.6; SizeZ_mm: 1.35; Value2: 0.25W; SizeArea_mm2: 5.12; CompType: Resistor; AEC Qualified: Y; VDC_V: 200V; AEC Category: Q200; AEC Grade: 0
R203 R207 R229 R253 R254 R264 = CRCW040256R2FKED: RES SMD 56.2 OHM 1% 1/16W 0402; Manufacturer: Yageo; CompType: Resistor; Value: 56.2; Value_Code: 56R2; Tolerance_%: 1; Power_W: 0.063; Value2: 0.063W; VDC_V: 50; TempCo: 100 ppm/C; SizeArea_mm2: 0.5; SizeZ_mm: 0.6; EIA_Code: E96; U/M: EA; AEC Category: Q200
R204 R215 = CRCW0402150KFKED: RES, 150 k, 1%, 0.063 W, 0402; Manufacturer: Vishay-Dale; CompType: Resistor; Value: 150k; Res_ohm: 150000; Tolerance_%: 1; Power_W: 0.063; Value2: 0.063W; VDC_V: 50; TempCo: 100 ppm/C; SizeArea_mm2: 0.5; SizeZ_mm: 0.6; EIA_Code: E96; U/M: EA; AEC Category: Q200; Green_Lifecycle: Active; Green_REACh: Passed
R206 = CRCW080528K7FKEA: RES, 28.7 k, 1%, 0.125 W, 0805; Manufacturer: Vishay-Dale; CompType: Resistor; Value: 28.7k; Res_ohm: 28700; Value_Code: 28k7; Tolerance_%: 1; Power_W: 0.125; Value2: 0.125W; VDC_V: 150; TempCo: 100 ppm/C; SizeArea_mm2: 2.5; SizeX_mm: 2; SizeY_mm: 1.25; SizeZ_mm: 1.45; EIA_Code: E96; U/M: EA; AEC Category: Q200
R208 R213 R216 R217 R256 R259 R261 R265 = CRCW040210K0FKED: RES, 10.0 k, 1%, 0.063 W, 0402; Manufacturer: Vishay-Dale; CompType: Resistor; Value: 10.0k; Res_ohm: 10000; Value_Code: 10k0; Tolerance_%: 1; Power_W: 0.063; Value2: 0.063W; VDC_V: 50; TempCo: 100 ppm/C; SizeArea_mm2: 0.5; SizeZ_mm: 0.6; EIA_Code: E96; U/M: EA; AEC Category: Q200; Green_Lifecycle: Active; Green_REACh: Passed
R209 R218 = CMP-0022243-4: RES, 25.5, 1%, 0.1 W, AEC-Q200 Grade 0, 0603; Manufacturer: Vishay-Dale; Power_W: 100mW; TempCo: 100 ppm/C; Value_Code: 25R5; Value: 25.5; EIA_Code: E96; SizeX_mm: 1.6; SizeY_mm: 0.8; SizeZ_mm: 1; Value2: 0.1W; SizeArea_mm2: 1.28; CompType: Resistor; AEC Qualified: Y; VDC_V: 75V; AEC Category: Q200; AEC Grade: 0
R211 = CRCW04021K24FKED: RES, 1.24 k, 1%, 0.063 W, 0402; Manufacturer: Vishay-Dale; CompType: Resistor; Value: 1.24k; Res_ohm: 1240; Value_Code: 1k24; Tolerance_%: 1; Power_W: 0.063; Value2: 0.063W; VDC_V: 50; TempCo: 100 ppm/C; SizeArea_mm2: 0.5; SizeZ_mm: 0.6; EIA_Code: E96; U/M: EA; AEC Category: Q200
R212 = CRCW060356R2FKEA: RES, 56.2, 1%, 0.1 W, 0603; Manufacturer: Vishay-Dale; CompType: Resistor; Value: 56.2; Value_Code: 56R2; Tolerance_%: 1; Power_W: 0.1; Value2: 0.1W; VDC_V: 75; TempCo: 100 ppm/C; SizeArea_mm2: 1.28; SizeX_mm: 1.6; SizeY_mm: 0.8; EIA_Code: E96; U/M: EA; AEC Category: Q200; Green_Lifecycle: Active; Green_REACh: Passed
R214 = CMP-0022512-4: RES, 5.49 k, 1%, 0.1 W, AEC-Q200 Grade 0, 0603; Manufacturer: Vishay-Dale; Power_W: 100mW; TempCo: 100 ppm/C; Value_Code: 5k49; Value: 5.49k; EIA_Code: E96; SizeX_mm: 1.6; SizeY_mm: 0.8; SizeZ_mm: 1; Value2: 0.1W; SizeArea_mm2: 1.28; CompType: Resistor; AEC Qualified: Y; VDC_V: 75V; AEC Category: Q200; AEC Grade: 0
R221 R222 = CRCW04024K99FKED: RES, 4.99 k, 1%, 0.063 W, 0402; Manufacturer: Vishay-Dale; CompType: Resistor; Value: 4.99k; Res_ohm: 4990; Value_Code: 4k99; Tolerance_%: 1; Power_W: 0.063; Value2: 0.063W; VDC_V: 50; TempCo: 100 ppm/C; SizeArea_mm2: 0.5; SizeZ_mm: 0.6; EIA_Code: E96; U/M: EA; AEC Category: Q200
R223 R224 = CRCW04029K31FKED: RES, 9.31 k, 1%, 0.063 W, 0402; Manufacturer: Vishay-Dale; CompType: Resistor; Value: 9.31k; Res_ohm: 9310; Value_Code: 9k31; Tolerance_%: 1; Power_W: 0.063; Value2: 0.063W; VDC_V: 50; TempCo: 100 ppm/C; SizeArea_mm2: 0.5; SizeZ_mm: 0.6; EIA_Code: E96; U/M: EA; AEC Category: Q200
R225 = CMP-0022599-4: RES, 7.15 k, 1%, 0.1 W, AEC-Q200 Grade 0, 0603; Manufacturer: Vishay-Dale; Power_W: 100mW; TempCo: 100 ppm/C; Value_Code: 7k15; Value: 7.15k; EIA_Code: E96; SizeX_mm: 1.6; SizeY_mm: 0.8; SizeZ_mm: 1; Value2: 0.1W; SizeArea_mm2: 1.28; CompType: Resistor; AEC Qualified: Y; VDC_V: 75V; AEC Category: Q200; AEC Grade: 0
R226 = CRCW060314K3FKEA: RES, 14.3 k, 1%, 0.1 W, 0603; Manufacturer: Vishay-Dale; CompType: Resistor; Value: 14.3k; Res_ohm: 14300; Value_Code: 14k3; Tolerance_%: 1; Power_W: 0.1; Value2: 0.1W; VDC_V: 75; TempCo: 100 ppm/C; SizeArea_mm2: 1.28; SizeX_mm: 1.6; SizeY_mm: 0.8; EIA_Code: E96; U/M: EA; AEC Category: Q200; Green_Lifecycle: Active; Green_REACh: Passed
R227 = CRCW06031K00FKEA: RES, 1.00 k, 1%, 0.1 W, 0603; Manufacturer: Vishay-Dale; CompType: Resistor; Value: 1.00k; Res_ohm: 1000; Value_Code: 1k00; Tolerance_%: 1; Power_W: 0.1; Value2: 0.1W; VDC_V: 75; TempCo: 100 ppm/C; SizeArea_mm2: 1.28; SizeX_mm: 1.6; SizeY_mm: 0.8; EIA_Code: E96; U/M: EA; AEC Category: Q200; Green_Lifecycle: Active; Green_REACh: Passed
R228 = CRCW060325R5FKEA: RES, 25.5, 1%, 0.1 W, 0603; Manufacturer: Vishay-Dale; CompType: Resistor; Value: 25.5; Value_Code: 25R5; Tolerance_%: 1; Power_W: 0.1; Value2: 0.1W; VDC_V: 75; TempCo: 100 ppm/C; SizeArea_mm2: 1.28; SizeX_mm: 1.6; SizeY_mm: 0.8; EIA_Code: E96; U/M: EA; AEC Category: Q200
R230 R235 = CRCW060339R2FKEA: RES, 39.2, 1%, 0.1 W, 0603; Manufacturer: Vishay-Dale; CompType: Resistor; Value: 39.2; Value_Code: 39R2; Tolerance_%: 1; Power_W: 0.1; Value2: 0.1W; VDC_V: 75; TempCo: 100 ppm/C; SizeArea_mm2: 1.28; SizeX_mm: 1.6; SizeY_mm: 0.8; EIA_Code: E96; U/M: EA; AEC Category: Q200
R231-R234 = CMP-0026739-1: RES, 4.70 k, 1%, 0.0625 W, 0402; Manufacturer: Yageo America; Power_W: 62.5mW; TempCo: 100 ppm/C; Value_Code: 4k70; U/M: EA; Value: 4.70k; Res_ohm: 4.7k; SizeX_mm: 1; SizeY_mm: 0.5; SizeZ_mm: 0.6; CompType: Resistor; AEC Qualified: N; VDC_V: 50V; AEC Category: Q200
R236 = CRCW04027K15FKED: RES, 7.15 k, 1%, 0.063 W, 0402; Manufacturer: Vishay-Dale; CompType: Resistor; Value: 7.15k; Res_ohm: 7150; Value_Code: 7k15; Tolerance_%: 1; Power_W: 0.063; Value2: 0.063W; VDC_V: 50; TempCo: 100 ppm/C; SizeArea_mm2: 0.5; SizeZ_mm: 0.6; EIA_Code: E96; U/M: EA; AEC Category: Q200; Green_Lifecycle: Active; Green_REACh: Passed
R237 R239 R240 = RC1206FR-072ML: RES, 2.00 M, 1%, 0.25 W, 1206; Manufacturer: Yageo America; CompType: Resistor; Value: 2.00Meg; Res_ohm: 2000000; Value_Code: 2M00; Tolerance_%: 1; Power_W: 0.25; Value2: 0.25W; VDC_V: 200; TempCo: 100 ppm/C; SizeArea_mm2: 5.12; SizeX_mm: 3.2; SizeY_mm: 1.6; SizeZ_mm: 1.35; EIA_Code: E96; U/M: EA; AEC Category: Q200; Green_Lifecycle: Active; Green_REACh: Passed
R238 R248 = CMP-0022635-4: RES, 8.25 k, 1%, 0.1 W, AEC-Q200 Grade 0, 0603; Manufacturer: Vishay-Dale; Power_W: 100mW; TempCo: 100 ppm/C; Value_Code: 8k25; Value: 8.25k; EIA_Code: E96; SizeX_mm: 1.6; SizeY_mm: 0.8; SizeZ_mm: 1; Value2: 0.1W; SizeArea_mm2: 1.28; CompType: Resistor; AEC Qualified: Y; VDC_V: 75V; AEC Category: Q200; AEC Grade: 0
R241 R247 R249-R252 = CRCW06030000Z0EA: RES, 0, 5%, 0.1 W, 0603; Manufacturer: Vishay-Dale; CompType: Resistor; Value: 0; Value_Code: 0000; Tolerance_%: 5; Power_W: 0.1; Value2: 0.1W; VDC_V: 75; TempCo: 200 ppm/C; SizeArea_mm2: 1.28; SizeX_mm: 1.6; SizeY_mm: 0.8; SizeZ_mm: 1; EIA_Code: E24; U/M: EA; AEC Category: Q200; Green_Lifecycle: Active; Green_REACh: Passed
R242-R245 = CMP-0022278-4: RES, 2.55 k, 1%, 0.1 W, AEC-Q200 Grade 0, 0603; Manufacturer: Vishay-Dale; Power_W: 100mW; TempCo: 100 ppm/C; Value_Code: 2k55; Value: 2.55k; EIA_Code: E96; SizeX_mm: 1.6; SizeY_mm: 0.8; SizeZ_mm: 1; Value2: 0.1W; SizeArea_mm2: 1.28; CompType: Resistor; AEC Qualified: Y; VDC_V: 75V; AEC Category: Q200; AEC Grade: 0
R246 = CMP-0022242-4: RES, 25.5 k, 1%, 0.1 W, AEC-Q200 Grade 0, 0603; Manufacturer: Vishay-Dale; Power_W: 100mW; TempCo: 100 ppm/C; Value_Code: 25k5; Value: 25.5k; EIA_Code: E96; SizeX_mm: 1.6; SizeY_mm: 0.8; SizeZ_mm: 1; Value2: 0.1W; SizeArea_mm2: 1.28; CompType: Resistor; AEC Qualified: Y; VDC_V: 75V; AEC Category: Q200; AEC Grade: 0
R255 R260 = CRCW04023K65FKED: RES, 3.65 k, 1%, 0.063 W, 0402; Manufacturer: Vishay-Dale; CompType: Resistor; Value: 3.65k; Res_ohm: 3650; Value_Code: 3k65; Tolerance_%: 1; Power_W: 0.063; Value2: 0.063W; VDC_V: 50; TempCo: 100 ppm/C; SizeArea_mm2: 0.5; SizeZ_mm: 0.6; EIA_Code: E96; U/M: EA; AEC Category: Q200
R257 R258 R262 R263 = CRCW04021K00FKED: RES, 1.00 k, 1%, 0.063 W, 0402; Manufacturer: Vishay-Dale; CompType: Resistor; Value: 1.00k; Res_ohm: 1000; Value_Code: 1k00; Tolerance_%: 1; Power_W: 0.063; Value2: 0.063W; VDC_V: 50; TempCo: 100 ppm/C; SizeArea_mm2: 0.5; SizeZ_mm: 0.6; EIA_Code: E96; U/M: EA; AEC Category: Q200; Green_Lifecycle: Active; Green_REACh: Passed
TP108 TP109 = 5000: Test Point, Miniature, Red, TH; Manufacturer: Keystone; CompType: Test Point Loop; ContactFinish: Silver; Green_Lifecycle: Active; Green_REACh: Passed
TP200-TP215 = 0312-0-15-15-34-27-10-0: Pin Receptacle, .032-.046" .075" Dia, Gold, TH; Manufacturer: Mill-Max; Gender: Female
U200 U210 U211 = CMP-0040149-1: IC OPAMP VFB 45MHZ RRO SOT23-5; PartNumber: LMV116MF/NOPB; Manufacturer: Texas Instruments; BW @ Acl(MHz): 205; Io(Typ)(mA): 50; 3rd Harmonic(dBc): 105; Number of Channels: 1; Iib(Max)(nA): 1000; 2nd Harmonic(dBc): 85
U201 U206 U209 = CMP-0040888-1: Precision, 20 MHz, 0.9 pA Ib, RRIO, CMOS Operational Amplifier, 1.8 to 5.5 V, -40 to 125 degC, 5-pin SOT23 (DBV5), Green (RoHS & no Sb/Br); Manufacturer: Texas Instruments; CMRR(Min)(dB): 100; Iq per channel(Max)(mA): 1.75; IIB(Max)(pA): 0.9; Total Supply Voltage(Min)(+5V is 5, +/-5V is 10): 1.8; Sub Family: High Output Current Amplifier (>=50mA), Low Input Bias Current Amp (<=10pA), Low Noise Amp (<=10nV/rtHz), Low Offset Voltage Amplifier (<=500uV), Low Supply Voltage Amplifier (<=2.7V), Precision Amplifier; Number of Channels: 2; Total Supply Voltage(Max)(+5V is 5, +/-5V is 10): 5.5; Offset Drift(Typ)(uV/C): 1.5; Vn at 1kHz(Typ)(nV/rtHz): 8.5; Slew Rate(Typ)(V/us): 10; Vio (25C)(Max)(mV): 0.15
U202 = TLV71333PQDBVRQ1: Capacitor-Free, 150-mA, Low-Dropout Regulator with Foldback Current Limit for Portable Devices, DBV0005A; Manufacturer: Texas Instruments; SymbolCreator: Altium; SizeArea_mm2: 8.12; SizeAreaWB_mm2: 14.82; SizeX_mm: 2.8; SizeY_mm: 2.9; SizeZ_mm: 1.45; CompType: IC; U/M: EA
U203 = CMP-0080587-1: Precision Reinforced Isolated Amplifier for Current Sensing, DWV0008A (SOIC-8); Alternate Manufacturer: Texas Instruments; SizeAreaWB_mm2: 105.975; SizeZ_mm: 2.8; SizeX_mm: 11.5; SizeY_mm: 5.85; SizeArea_mm2: 67.275; CompType: IC; AEC Qualified: Y; AEC Category: Q200
U204 U208 = CMP-0076069-2: High-Immunity, 5.7kVRMS Reinforced Dual-Channel 2/0 Digital Isolator, 100Mbps, DW0016B (SOIC-16); Manufacturer: Texas Instruments; SizeZ_mm: 2.65; SizeX_mm: 10.4; SizeY_mm: 10.3; SizeArea_mm2: 107.12; CompType: IC; U/M: EA; SizeAreaWB_mm2: 152.52
U205 = CMP-0066190-1: Low-Drift, Low-Power, Dual-Output VREF and VREF/2 Voltage Reference, DDC0005A (SOT-23-T-5); Alternate PartNumber: REF2033AIDDCT; Alternate Manufacturer: Texas Instruments; SizeAreaWB_mm2: 14.82; U/M: EA; SizeZ_mm: 1.1; SizeX_mm: 2.8; SizeY_mm: 2.9; SizeArea_mm2: 8.12; CompType: IC
U207 = CMP-0078341-1: Precision, 2-V Input, Reinforced Isolated Amplifier, DWV0008A (SOIC-8); Alternate Manufacturer: Texas Instruments; SizeAreaWB_mm2: 105.975; SizeZ_mm: 2.8; SizeX_mm: 11.5; SizeY_mm: 5.85; SizeArea_mm2: 67.275; CompType: IC; AEC Qualified: N; AEC Category: Q200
